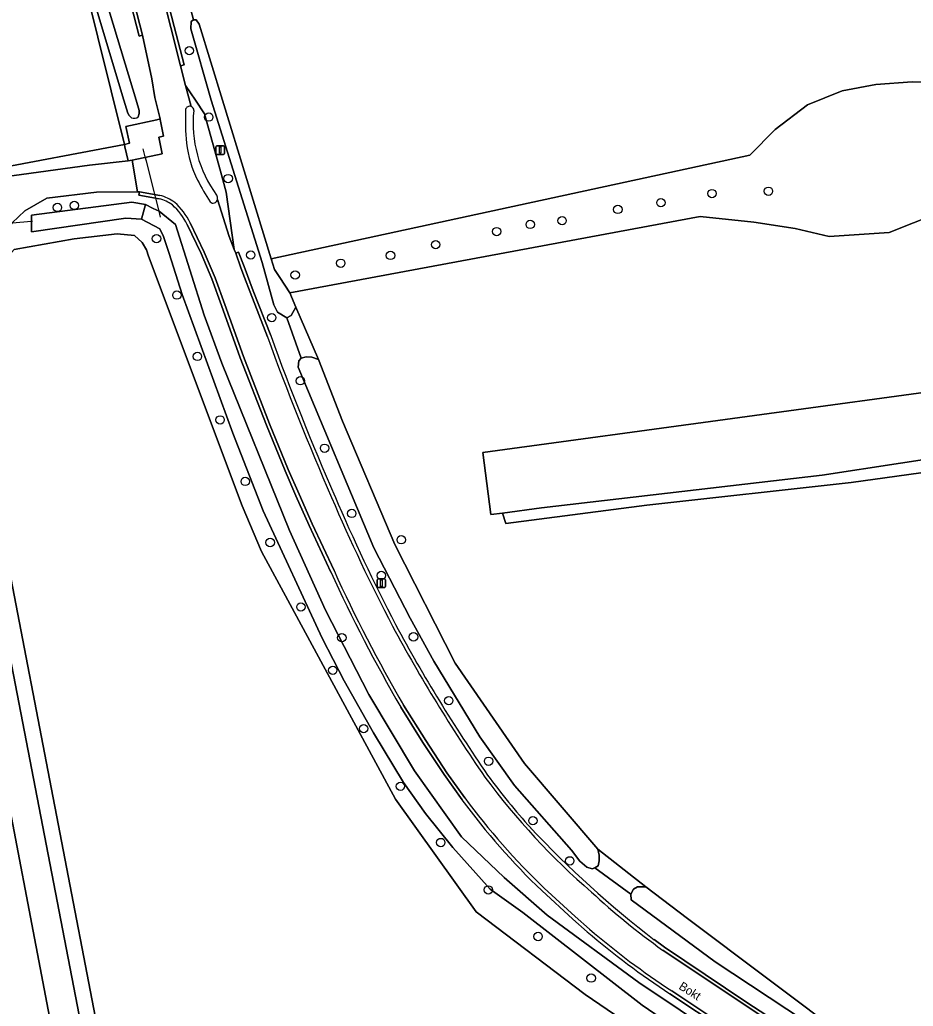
# Model space of a CAD drawing. Extents: x 162510 to 163918, y 388494 to 389774.
# Drawn here: x 163137.8 to 163242.1, y 389394.3 to 389509.4 of the extents above; entities that cross this region are included whole.
import ezdxf

# ---------------------------------------------------------------- set-up
doc = ezdxf.new("R2010")
doc.units = 0
for name, color, linetype in [('IMGEO_Boom', 7, 'Continuous'), ('IMGEO_Bouwland', 7, 'Continuous'), ('IMGEO_Duiker', 7, 'Continuous'), ('IMGEO_Fietspad_open', 7, 'Continuous'), ('IMGEO_Grasland_agrarisch', 7, 'Continuous'), ('IMGEO_Grasland_overig', 7, 'Continuous'), ('IMGEO_Groenvoorziening', 7, 'Continuous'), ('IMGEO_Lichtmast', 7, 'Continuous'), ('IMGEO_Loofbos', 7, 'Continuous'), ('IMGEO_Openbare_ruimte_label', 7, 'Continuous'), ('IMGEO_Rijbaan_lokaal_gesloten', 7, 'Continuous'), ('IMGEO_Rijbaan_lokaal_halfverhard', 7, 'Continuous'), ('IMGEO_Verkeersbordpaal', 7, 'Continuous'), ('IMGEO_Verkeerseiland_open', 7, 'Continuous'), ('IMGEO_Waterloop', 7, 'Continuous')]:
    doc.layers.add(name, color=color, linetype=linetype)

msp = doc.modelspace()

# ---------------------------------------------------------------- linework, layer by layer
at = {"layer": 'IMGEO_Boom'}
for centre in [(163157.61, 389505.79), (163159.88, 389498.04), (163162.14, 389490.86), (163225.16, 389489.39), (163212.62, 389488.05), (163218.58, 389489.11), (163142.22, 389487.5), (163144.2, 389487.73), (163207.6, 389487.26), (163201.09, 389485.95), (163193.46, 389484.68), (163197.38, 389485.51), (163153.78, 389483.85), (163186.35, 389483.15), (163164.78, 389481.94), (163181.08, 389481.9), (163175.28, 389480.98), (163169.96, 389479.61), (163156.16, 389477.26), (163167.23, 389474.63), (163158.55, 389470.1), (163170.56, 389467.27), (163161.2, 389462.7), (163173.39, 389459.39), (163164.13, 389455.52), (163176.56, 389451.78), (163167.04, 389448.39), (163182.33, 389448.71), (163180.01, 389444.54), (163170.63, 389440.86), (163175.4, 389437.28), (163183.76, 389437.38), (163174.34, 389433.47), (163187.87, 389429.93), (163177.95, 389426.66), (163192.52, 389422.86), (163182.23, 389419.93), (163197.69, 389415.92), (163186.94, 389413.37), (163201.99, 389411.23), (163192.49, 389407.84), (163198.3, 389402.4), (163204.49, 389397.55)]:
    msp.add_circle(centre, 0.489, dxfattribs=at)
at = {"layer": 'IMGEO_Bouwland'}
for points in [[(163081.43, 389571.51), (163036.71, 389569.51), (163036.92, 389568.46), (163034.88, 389568.4), (163038.38, 389551.87), (163041.39, 389540.2), (163045.34, 389519.55), (163052.45, 389485.98), (163058.34, 389486.21), (163065.74, 389486.65), (163069.57, 389487.13), (163075.69, 389486.8), (163079.71, 389487.2), (163100.6, 389488.5), (163120.69, 389490.42), (163133.94, 389491.79), (163150.04, 389494.85), (163145.4, 389513.69), (163141.61, 389528.41), (163137.44, 389544.71), (163136.05, 389551.14), (163125.86, 389549.68), (163092.55, 389544.33), (163089.11, 389543.77)], [(163130.44, 389477.03), (163153.34, 389358.11), (163156.41, 389358.71), (163204.24, 389366.94), (163238.68, 389372.36), (163230.21, 389377.63), (163203.79, 389395.63), (163191.08, 389405.29), (163181.67, 389418.44), (163166.02, 389447.32), (163163.76, 389452.65), (163152.85, 389481.8), (163152.6, 389482.56), (163152.11, 389483.42), (163151.22, 389484.22), (163149.18, 389484.42), (163144.19, 389483.83), (163137.19, 389482.57), (163133.75, 389478.83), (163132.04, 389477.85)]]:
    msp.add_lwpolyline(points, close=True, dxfattribs=at)
at = {"layer": 'IMGEO_Duiker'}
for points in [[(163154.25, 389486.37), (163154.08, 389487.04), (163153.69, 389488.57), (163153.49, 389489.34), (163152.6, 389492.88), (163152.47, 389493.39), (163152.39, 389493.7), (163152.22, 389494.35)], [(163130.2, 389485.09), (163131.18, 389485.18), (163136.96, 389485.69), (163139.19, 389485.89), (163139.31, 389485.9)]]:
    msp.add_lwpolyline(points, dxfattribs=at)
at = {"layer": 'IMGEO_Fietspad_open'}
msp.add_lwpolyline([(163160.88, 389488.43), (163162.27, 389484.09), (163162.86, 389482.59), (163161.91, 389489.27), (163161.23, 389491.73), (163159.38, 389498.43), (163158.32, 389500), (163157.18, 389501.71), (163157.81, 389499.28)], dxfattribs=at)
for centre, radius, start, end in [((163157.68, 389498.85), 0.451, 353.6982, 73.241), ((163172.43, 389497.37), 14.38, 174.3099, 215.996), ((163160.45, 389488.61), 0.469, 336.826, 41.3455)]:
    msp.add_arc(centre, radius, start, end, dxfattribs=at)
at = {"layer": 'IMGEO_Grasland_agrarisch'}
for points in [[(163156.83, 389514.22), (163158.11, 389509.39), (163158.42, 389509.4), (163158.77, 389508.89), (163161.49, 389500), (163167.14, 389481.5), (163223.01, 389493.61), (163225.94, 389496.58), (163229.71, 389499.46), (163233.77, 389501.12), (163237.68, 389501.84), (163241.93, 389502.15), (163246.08, 389502.04), (163250.53, 389501.21), (163257.76, 389497.78), (163277.39, 389500.8), (163275.96, 389508.95), (163278.11, 389509.29), (163277.26, 389514.04)], [(163256.1, 389491.27), (163239.24, 389484.57), (163232.24, 389484.12), (163228.28, 389485.02), (163223.48, 389485.77), (163217.21, 389486.45), (163169.34, 389477.53), (163170.05, 389475.86), (163172.68, 389469.73), (163175.47, 389462.53), (163181.58, 389448.15), (163188.63, 389434.29), (163196.7, 389422.61), (163205.28, 389412.58), (163210.88, 389408.18), (163215.73, 389404.52), (163234.64, 389390.29), (163247.27, 389382.49)], [(163245.49, 389456.85), (163234.81, 389455.4), (163210.99, 389452.76), (163194.55, 389450.59), (163194.14, 389451.83), (163192.77, 389451.65), (163191.84, 389458.88), (163250.09, 389466.84)]]:
    msp.add_lwpolyline(points, dxfattribs=at)
at = {"layer": 'IMGEO_Grasland_overig'}
for points in [[(163144.21, 389557.44), (163144.91, 389554.2), (163146.38, 389547.39), (163147.78, 389541.4), (163149.4, 389534.42), (163151.14, 389527.46), (163152.98, 389519.86), (163155.23, 389511.03), (163155.86, 389508.6), (163156.99, 389504.14), (163156.58, 389504.03), (163157.18, 389501.71), (163158.32, 389500), (163159.38, 389498.43), (163161.23, 389491.73), (163161.91, 389489.27), (163162.86, 389482.59), (163163.02, 389482.16), (163163.36, 389482.27), (163164, 389480.59), (163165.07, 389477.78), (163167.1, 389472.53)], [(163229.37, 389392.56), (163218.97, 389399.45), (163209.16, 389406.67), (163209.11, 389407.35), (163204.93, 389410.41), (163204.59, 389410.29), (163203.99, 389410.5), (163203.18, 389411.19), (163202.2, 389412.47), (163195.54, 389420.02), (163191.5, 389425.69), (163186.14, 389434.53), (163183.37, 389439.55), (163179.12, 389447.77), (163170.32, 389468.84), (163170.4, 389469.6), (163170.64, 389469.9), (163168.98, 389474.6), (163167.89, 389475.29), (163167.46, 389476.11), (163166.09, 389481.07), (163160.17, 389500), (163157.8, 389508.34), (163157.83, 389509.2), (163158.11, 389509.39), (163156.83, 389514.22)], [(163246.08, 389502.04), (163241.93, 389502.15), (163237.68, 389501.84), (163233.77, 389501.12), (163229.71, 389499.46), (163225.94, 389496.58), (163223.01, 389493.61), (163167.14, 389481.5), (163167.53, 389480.24), (163168.15, 389479.3), (163169.34, 389477.53), (163217.21, 389486.45), (163223.48, 389485.77), (163228.28, 389485.02), (163232.24, 389484.12), (163239.24, 389484.57), (163256.1, 389491.27)], [(163115.04, 389488.17), (163145.97, 389492.41), (163150.46, 389492.95), (163150.1, 389494.57), (163150.04, 389494.85), (163133.94, 389491.79)], [(163154.1, 389488.5), (163151.71, 389488.92), (163151.78, 389489.31), (163151.57, 389489.32), (163146.77, 389489.28), (163141, 389488.59), (163138.42, 389487.08), (163136.96, 389485.69), (163135.11, 389482.97)], [(163228.8, 389381.84), (163210.45, 389394.39), (163196.52, 389405.21), (163192.71, 389407.91), (163188.34, 389412.77), (163185.17, 389416.76), (163182.61, 389420.39), (163179.11, 389426.18), (163175.68, 389432.23), (163173.11, 389437.23), (163166.24, 389452.1), (163162.68, 389461.14), (163156.77, 389477.34), (163155.26, 389482.1), (163154.61, 389484.12), (163154.16, 389485.01), (163152.04, 389486.12), (163150.19, 389486.24), (163139.2, 389484.65), (163139.19, 389485.89), (163139.19, 389486.58), (163150.89, 389488.12), (163152.49, 389487.83), (163153.39, 389487.38), (163154.08, 389487.04), (163155.98, 389485.49), (163159.33, 389474.91), (163161.39, 389469.3), (163169.31, 389449.78), (163173.5, 389440.5), (163178.57, 389430.66), (163183.89, 389421.75), (163189.35, 389414.03), (163194.35, 389409.29), (163199.34, 389404.88), (163210.06, 389397.04), (163234.4, 389380.75)], [(163174.13, 389444.94), (163171.6, 389450.38), (163170.04, 389453.85), (163168.79, 389456.76), (163166.6, 389462.09), (163163.55, 389469.96), (163161.36, 389476.04), (163160.23, 389479.15), (163158.98, 389482.13), (163157.35, 389485.52)], [(163129.61, 389479.11), (163130.2, 389478.28), (163130.44, 389477.03), (163132.04, 389477.85), (163133.75, 389478.83), (163137.19, 389482.57), (163144.19, 389483.83), (163149.18, 389484.42), (163151.22, 389484.22), (163152.11, 389483.42), (163152.6, 389482.56), (163152.85, 389481.8), (163163.76, 389452.65), (163166.02, 389447.32), (163181.67, 389418.44), (163191.08, 389405.29), (163203.79, 389395.63), (163230.21, 389377.63), (163238.68, 389372.36), (163241.51, 389372.81), (163228.8, 389381.84)], [(163189.42, 389418.36), (163187.33, 389421.29), (163184.87, 389425.04), (163182.27, 389429.18)], [(163204.04, 389402.95), (163202.36, 389404.44), (163198.73, 389407.76)], [(163211.84, 389402.04), (163213.05, 389401.15), (163222.54, 389394.79), (163229.33, 389390.35), (163235.11, 389386.58), (163240.77, 389382.94), (163242.65, 389381.73)], [(163247, 389373.49), (163244.56, 389375.34), (163242.24, 389376.99), (163238.57, 389379.42), (163234.65, 389382.03), (163227.76, 389386.53), (163219.99, 389391.51), (163213.66, 389395.72)]]:
    msp.add_lwpolyline(points, dxfattribs=at)
for points in [[(163130.2, 389478.28), (163129.61, 389479.11), (163124.76, 389478.3), (163124.83, 389477.66), (163125.15, 389475.81), (163125.49, 389475.87), (163150.89, 389342.64), (163162.52, 389344.71), (163162.24, 389346.25), (163159.32, 389345.69), (163158.79, 389345.7), (163158.26, 389345.91), (163157.88, 389346.64), (163157.84, 389347.71), (163158.46, 389348.72), (163202.61, 389356.33), (163232.25, 389361.83), (163251.18, 389365.49), (163246.08, 389369.56), (163157.64, 389352.72), (163154.49, 389352.12), (163154.8, 389350.51), (163153.04, 389350.25), (163128.35, 389478.1)], [(163194.14, 389451.83), (163198.7, 389452.44), (163231.44, 389456.24), (163249.7, 389459.05), (163258.06, 389461.07), (163271.21, 389463.32), (163287.72, 389465.23), (163330.79, 389471.14), (163330.51, 389476.51), (163296.77, 389472.48), (163250.09, 389466.84), (163191.84, 389458.88), (163192.77, 389451.65)], [(163168.98, 389474.6), (163170.64, 389469.9), (163171.24, 389470.07), (163171.91, 389470.03), (163172.68, 389469.73), (163170.05, 389475.86), (163169.49, 389474.89)], [(163209.11, 389407.35), (163209.42, 389407.91), (163209.91, 389408.2), (163210.88, 389408.18), (163205.28, 389412.58), (163205.42, 389411.89), (163205.41, 389411.22), (163205.29, 389410.64), (163204.93, 389410.41)]]:
    msp.add_lwpolyline(points, close=True, dxfattribs=at)
for centre, radius, start, end in [((163153.01, 389484.17), 4.47, 54.0478, 75.9062), ((163150.59, 389482.18), 7.54, 26.2296, 47.9694), ((163476.38, 389585.05), 329.11, 199.9917, 203.5013), ((163379.15, 389541.52), 222.59, 203.2041, 207.4774), ((163334.65, 389517.92), 176.33, 204.4467, 210.2143), ((163350.38, 389529.83), 191.7, 208.3454, 214.4997), ((163254.37, 389466.74), 76.88, 216.2816, 222.2161), ((163254.19, 389465.87), 80.33, 216.2634, 226.34), ((163283.57, 389495.71), 117.99, 223.1077, 232.5563), ((163266.36, 389475.96), 95.99, 229.5121, 236.7024)]:
    msp.add_arc(centre, radius, start, end, dxfattribs=at)
at = {"layer": 'IMGEO_Groenvoorziening'}
for points in [[(163150.88, 389497.95), (163150.59, 389498.21), (163150.43, 389498.5), (163149.97, 389500), (163145.86, 389513.8), (163143.43, 389523.47), (163138.76, 389543.95), (163138.69, 389544.49), (163138.87, 389544.87), (163139.27, 389545.12), (163139.31, 389545.14), (163139.84, 389544.96), (163140.11, 389544.42), (163147.45, 389513.15), (163151.39, 389500)], [(163145.4, 389513.69), (163150.04, 389494.85), (163150.63, 389494.98), (163150.21, 389496.94), (163153.83, 389497.73), (163154.2, 389497.82), (163153.6, 389500.31), (163153.24, 389502.51), (163152.16, 389507.6), (163151.77, 389507.5), (163150.79, 389511.27)], [(163151.39, 389500), (163151.74, 389498.8), (163151.77, 389498.44), (163151.64, 389498.06)]]:
    msp.add_lwpolyline(points, dxfattribs=at)
msp.add_arc((163151.17, 389498.65), 0.755, 247.6026, 308.8473, dxfattribs=at)
at = {"layer": 'IMGEO_Lichtmast'}
for p, q in [((163160.72, 389493.79), (163160.72, 389494.58)), ((163160.72, 389494.58), (163160.72, 389493.79)), ((163160.82, 389494.68), (163161.61, 389494.68)), ((163161.61, 389494.68), (163160.82, 389494.68)), ((163161.71, 389494.58), (163161.71, 389493.79)), ((163161.71, 389493.79), (163161.71, 389494.58)), ((163161.61, 389493.69), (163160.82, 389493.69)), ((163160.82, 389493.69), (163161.61, 389493.69))]:
    msp.add_line(p, q, dxfattribs=at)
msp.add_lwpolyline([(163161.14, 389494.56), (163161.29, 389494.56), (163161.29, 389493.81), (163161.14, 389493.81), (163161.14, 389494.56)], dxfattribs=at)
for centre, start, end in [((163160.82, 389494.58), 90, 180), ((163160.82, 389494.58), 90, 180), ((163161.61, 389494.58), 0, 90), ((163161.61, 389494.58), 360, 90), ((163160.82, 389493.79), 180, 270), ((163160.82, 389493.79), 180, 270), ((163161.61, 389493.79), 270, 0), ((163161.61, 389493.79), 270, 0)]:
    msp.add_arc(centre, 0.1, start, end, dxfattribs=at)
at = {"layer": 'IMGEO_Loofbos'}
msp.add_lwpolyline([(163125.49, 389475.87), (163125.15, 389475.81), (163122, 389475.18), (163120.06, 389474.46), (163120.23, 389472.86), (163119.35, 389472.7), (163119.52, 389471.84), (163144.7, 389341.54), (163150.89, 389342.64)], close=True, dxfattribs=at)
at = {"layer": 'IMGEO_Rijbaan_lokaal_gesloten'}
for points in [[(163157.81, 389499.28), (163157.18, 389501.71), (163156.58, 389504.03), (163155.47, 389508.5), (163154.85, 389510.93), (163152.59, 389519.76), (163150.76, 389527.36), (163149.01, 389534.33), (163147.39, 389541.31), (163145.99, 389547.31), (163144.52, 389554.12), (163143.82, 389557.35)], [(163151.18, 389511.37), (163152.16, 389507.6), (163153.24, 389502.51), (163153.6, 389500.31), (163154.2, 389497.82), (163154.21, 389497.76), (163154.59, 389495.82), (163154.04, 389495.7), (163154.45, 389493.75), (163150.94, 389493.01), (163151.57, 389489.32), (163151.78, 389489.31), (163154.17, 389488.9)], [(163166.72, 389472.39), (163164.7, 389477.61), (163164.05, 389479.33), (163163.62, 389480.45), (163163.02, 389482.16), (163162.86, 389482.59), (163162.27, 389484.09), (163160.88, 389488.43)], [(163157.71, 389485.69), (163159.35, 389482.29), (163160.61, 389479.29), (163161.74, 389476.18), (163163.93, 389470.1), (163166.97, 389462.24), (163169.16, 389456.91), (163170.41, 389454.02), (163171.96, 389450.55), (163174.49, 389445.11)], [(163182.61, 389429.39), (163185.2, 389425.26), (163187.66, 389421.52), (163189.74, 389418.59)], [(163199, 389408.05), (163202.63, 389404.74), (163204.3, 389403.25)], [(163213.89, 389396.06), (163220.21, 389391.84), (163227.97, 389386.86), (163234.87, 389382.36), (163238.79, 389379.76), (163240.55, 389382.6), (163234.89, 389386.24), (163229.12, 389390.01), (163222.32, 389394.46), (163212.83, 389400.82)]]:
    msp.add_lwpolyline(points, dxfattribs=at)
msp.add_lwpolyline([(163154.2, 389497.82), (163153.83, 389497.73), (163150.21, 389496.94), (163150.63, 389494.98), (163150.04, 389494.85), (163150.1, 389494.57), (163150.46, 389492.95), (163150.94, 389493.01), (163154.45, 389493.75), (163154.04, 389495.7), (163154.59, 389495.82), (163154.21, 389497.76)], close=True, dxfattribs=at)
for centre, radius, start, end in [((163184.59, 389497.83), 27.44, 177.6954, 185.9172), ((163157.66, 389498.8), 0.502, 71.8749, 164.9821), ((163169.23, 389496.19), 11.99, 185.6746, 207.3539), ((163188.31, 389506.03), 33.46, 207.3125, 212.3371), ((163153.03, 389484.22), 4.81, 53.3361, 76.338), ((163150.62, 389482.21), 7.9, 26.1384, 48.0368), ((163160.38, 389488.5), 0.504, 226.342, 352.5452), ((163476.5, 389585.1), 329.65, 199.9932, 203.4999), ((163378.64, 389541.27), 222.43, 203.199, 207.4845), ((163334.66, 389517.92), 175.94, 204.4453, 210.2086), ((163350.56, 389529.93), 192.3, 208.3482, 214.5001), ((163258.57, 389470.17), 82.69, 216.4795, 229.1912), ((163254.22, 389465.89), 79.96, 216.2625, 226.3283), ((163262.81, 389470.68), 85.9, 227.2682, 234.4143), ((163266.33, 389475.91), 95.54, 229.5111, 236.7071)]:
    msp.add_arc(centre, radius, start, end, dxfattribs=at)
at = {"layer": 'IMGEO_Rijbaan_lokaal_halfverhard'}
for points in [[(163143.82, 389557.35), (163144.52, 389554.12), (163145.99, 389547.31), (163147.39, 389541.31), (163149.01, 389534.33), (163150.76, 389527.36), (163152.59, 389519.76), (163154.85, 389510.93), (163155.47, 389508.5), (163156.58, 389504.03), (163156.99, 389504.14), (163155.86, 389508.6), (163155.23, 389511.03), (163152.98, 389519.86), (163151.14, 389527.46), (163149.4, 389534.42), (163147.78, 389541.4), (163146.38, 389547.39), (163144.91, 389554.2), (163144.21, 389557.44)], [(163150.79, 389511.27), (163151.77, 389507.5), (163152.16, 389507.6), (163151.18, 389511.37)], [(163136.96, 389485.69), (163138.42, 389487.08), (163141, 389488.59), (163146.77, 389489.28), (163151.57, 389489.32), (163150.94, 389493.01), (163150.46, 389492.95), (163145.97, 389492.41), (163115.04, 389488.17)], [(163151.78, 389489.31), (163151.71, 389488.92), (163154.1, 389488.5)], [(163154.17, 389488.9), (163151.78, 389489.31)], [(163157.35, 389485.52), (163158.98, 389482.13), (163160.23, 389479.15), (163161.36, 389476.04), (163163.55, 389469.96), (163166.6, 389462.09), (163168.79, 389456.76), (163170.04, 389453.85), (163171.6, 389450.38), (163174.13, 389444.94)], [(163174.49, 389445.11), (163171.96, 389450.55), (163170.41, 389454.02), (163169.16, 389456.91), (163166.97, 389462.24), (163163.93, 389470.1), (163161.74, 389476.18), (163160.61, 389479.29), (163159.35, 389482.29), (163157.71, 389485.69)], [(163163.36, 389482.27), (163163.02, 389482.16), (163163.62, 389480.45), (163164.05, 389479.33), (163164.7, 389477.61), (163166.72, 389472.39)], [(163167.1, 389472.53), (163165.07, 389477.78), (163164, 389480.59), (163163.36, 389482.27)], [(163182.27, 389429.18), (163184.87, 389425.04), (163187.33, 389421.29), (163189.42, 389418.36)], [(163189.74, 389418.59), (163187.66, 389421.52), (163185.2, 389425.26), (163182.61, 389429.39)], [(163204.3, 389403.25), (163202.63, 389404.74), (163199, 389408.05)], [(163198.73, 389407.76), (163202.36, 389404.44), (163204.04, 389402.95)], [(163212.83, 389400.82), (163222.32, 389394.46), (163229.12, 389390.01), (163234.89, 389386.24), (163240.55, 389382.6), (163240.77, 389382.94), (163235.11, 389386.58), (163229.33, 389390.35), (163222.54, 389394.79), (163213.05, 389401.15), (163211.84, 389402.04)], [(163213.66, 389395.72), (163219.99, 389391.51), (163227.76, 389386.53), (163234.65, 389382.03), (163238.57, 389379.42), (163238.79, 389379.76), (163234.87, 389382.36), (163227.97, 389386.86), (163220.21, 389391.84), (163213.89, 389396.06)]]:
    msp.add_lwpolyline(points, dxfattribs=at)
for centre, radius, start, end in [((163153.03, 389484.22), 4.81, 53.3361, 76.338), ((163153.01, 389484.17), 4.47, 54.0478, 75.9062), ((163150.59, 389482.18), 7.54, 26.2296, 47.9694), ((163150.62, 389482.21), 7.9, 26.1384, 48.0368), ((163476.38, 389585.05), 329.11, 199.9917, 203.5013), ((163476.5, 389585.1), 329.65, 199.9932, 203.4999), ((163378.64, 389541.27), 222.43, 203.199, 207.4845), ((163379.15, 389541.52), 222.59, 203.2041, 207.4774), ((163334.65, 389517.92), 176.33, 204.4467, 210.2143), ((163334.66, 389517.92), 175.94, 204.4453, 210.2086), ((163350.56, 389529.93), 192.3, 208.3482, 214.5001), ((163350.38, 389529.83), 191.7, 208.3454, 214.4997), ((163258.57, 389470.17), 82.69, 216.4795, 229.1912), ((163254.37, 389466.74), 76.88, 216.2816, 222.2161), ((163254.19, 389465.87), 80.33, 216.2634, 226.34), ((163254.22, 389465.89), 79.96, 216.2625, 226.3283), ((163283.57, 389495.71), 117.99, 223.1077, 232.5563), ((163262.81, 389470.68), 85.9, 227.2682, 234.4143), ((163266.36, 389475.96), 95.99, 229.5121, 236.7024), ((163266.33, 389475.91), 95.54, 229.5111, 236.7071)]:
    msp.add_arc(centre, radius, start, end, dxfattribs=at)
at = {"layer": 'IMGEO_Verkeersbordpaal'}
for p, q in [((163179.52, 389443.24), (163179.52, 389444.04)), ((163179.52, 389444.04), (163179.52, 389443.24)), ((163179.62, 389444.14), (163180.4, 389444.14)), ((163180.4, 389444.14), (163179.62, 389444.14)), ((163180.5, 389444.04), (163180.5, 389443.24)), ((163180.5, 389443.24), (163180.5, 389444.04)), ((163180.4, 389443.14), (163179.62, 389443.14)), ((163179.62, 389443.14), (163180.4, 389443.14))]:
    msp.add_line(p, q, dxfattribs=at)
msp.add_lwpolyline([(163179.93, 389444.02), (163180.09, 389444.02), (163180.09, 389443.27), (163179.93, 389443.27), (163179.93, 389444.02)], dxfattribs=at)
for centre, start, end in [((163179.62, 389444.04), 90, 180), ((163179.62, 389444.04), 90, 180), ((163180.4, 389444.04), 0, 90), ((163180.4, 389444.04), 360, 90), ((163179.62, 389443.24), 180, 270), ((163179.62, 389443.24), 180, 270), ((163180.4, 389443.24), 270, 0), ((163180.4, 389443.24), 270, 0)]:
    msp.add_arc(centre, 0.1, start, end, dxfattribs=at)
at = {"layer": 'IMGEO_Verkeerseiland_open'}
for centre, radius, start, end in [((163184.59, 389497.83), 27.44, 177.6954, 185.9172), ((163157.66, 389498.8), 0.502, 71.8749, 164.9821), ((163157.68, 389498.85), 0.451, 353.6982, 73.241), ((163172.43, 389497.37), 14.38, 174.3099, 215.996), ((163169.23, 389496.19), 11.99, 185.6746, 207.3539), ((163188.31, 389506.03), 33.46, 207.3125, 212.3371), ((163160.45, 389488.61), 0.469, 336.826, 41.3455), ((163160.38, 389488.5), 0.504, 226.342, 352.5452)]:
    msp.add_arc(centre, radius, start, end, dxfattribs=at)
at = {"layer": 'IMGEO_Waterloop'}
for points in [[(163140.11, 389544.42), (163139.84, 389544.96), (163139.31, 389545.14), (163139.27, 389545.12), (163138.87, 389544.87), (163138.69, 389544.49), (163138.76, 389543.95), (163143.43, 389523.47), (163145.86, 389513.8), (163149.97, 389500), (163150.43, 389498.5), (163150.59, 389498.21), (163150.88, 389497.95)], [(163151.64, 389498.06), (163151.77, 389498.44), (163151.74, 389498.8), (163151.39, 389500), (163147.45, 389513.15), (163140.11, 389544.42)], [(163234.4, 389380.75), (163210.06, 389397.04), (163199.34, 389404.88), (163194.35, 389409.29), (163189.35, 389414.03), (163183.89, 389421.75), (163178.57, 389430.66), (163173.5, 389440.5), (163169.31, 389449.78), (163161.39, 389469.3), (163159.33, 389474.91), (163155.98, 389485.49), (163154.08, 389487.04), (163153.39, 389487.38), (163152.49, 389487.83), (163152.04, 389486.12), (163154.16, 389485.01), (163154.61, 389484.12), (163155.26, 389482.1), (163156.77, 389477.34), (163162.68, 389461.14), (163166.24, 389452.1), (163173.11, 389437.23), (163175.68, 389432.23), (163179.11, 389426.18), (163182.61, 389420.39), (163185.17, 389416.76), (163188.34, 389412.77), (163192.71, 389407.91), (163196.52, 389405.21), (163210.45, 389394.39), (163228.8, 389381.84)], [(163249.7, 389459.05), (163231.44, 389456.24), (163198.7, 389452.44), (163194.14, 389451.83), (163194.55, 389450.59), (163210.99, 389452.76), (163234.81, 389455.4), (163245.49, 389456.85)]]:
    msp.add_lwpolyline(points, dxfattribs=at)
for points in [[(163158.11, 389509.39), (163157.83, 389509.2), (163157.8, 389508.34), (163160.17, 389500), (163166.09, 389481.07), (163167.46, 389476.11), (163167.89, 389475.29), (163168.98, 389474.6), (163169.49, 389474.89), (163170.05, 389475.86), (163169.34, 389477.53), (163168.15, 389479.3), (163167.53, 389480.24), (163167.14, 389481.5), (163161.49, 389500), (163158.77, 389508.89), (163158.42, 389509.4)], [(163152.04, 389486.12), (163152.49, 389487.83), (163150.89, 389488.12), (163139.19, 389486.58), (163139.19, 389485.89), (163139.2, 389484.65), (163150.19, 389486.24)], [(163130.44, 389477.03), (163130.2, 389478.28), (163128.35, 389478.1), (163153.04, 389350.25), (163154.8, 389350.51), (163154.49, 389352.12), (163153.34, 389358.11)], [(163170.64, 389469.9), (163170.4, 389469.6), (163170.32, 389468.84), (163179.12, 389447.77), (163183.37, 389439.55), (163186.14, 389434.53), (163191.5, 389425.69), (163195.54, 389420.02), (163202.2, 389412.47), (163203.18, 389411.19), (163203.99, 389410.5), (163204.59, 389410.29), (163204.93, 389410.41), (163205.29, 389410.64), (163205.41, 389411.22), (163205.42, 389411.89), (163205.28, 389412.58), (163196.7, 389422.61), (163188.63, 389434.29), (163181.58, 389448.15), (163175.47, 389462.53), (163172.68, 389469.73), (163171.91, 389470.03), (163171.24, 389470.07)], [(163248.43, 389381.03), (163248.42, 389381.33), (163247.27, 389382.49), (163234.64, 389390.29), (163215.73, 389404.52), (163210.88, 389408.18), (163209.91, 389408.2), (163209.42, 389407.91), (163209.11, 389407.35), (163209.16, 389406.67), (163218.97, 389399.45), (163229.37, 389392.56), (163247.18, 389381.17), (163247.96, 389380.86), (163248.37, 389380.88)]]:
    msp.add_lwpolyline(points, close=True, dxfattribs=at)
msp.add_arc((163151.17, 389498.65), 0.755, 247.6026, 308.8473, dxfattribs=at)

# ---------------------------------------------------------------- texts
at = {"layer": 'IMGEO_Openbare_ruimte_label'}
msp.add_text('Bokt', height=1, rotation=327.5816, dxfattribs=at).set_placement((163214.62, 389396.34))

doc.saveas('drawing.dxf')
